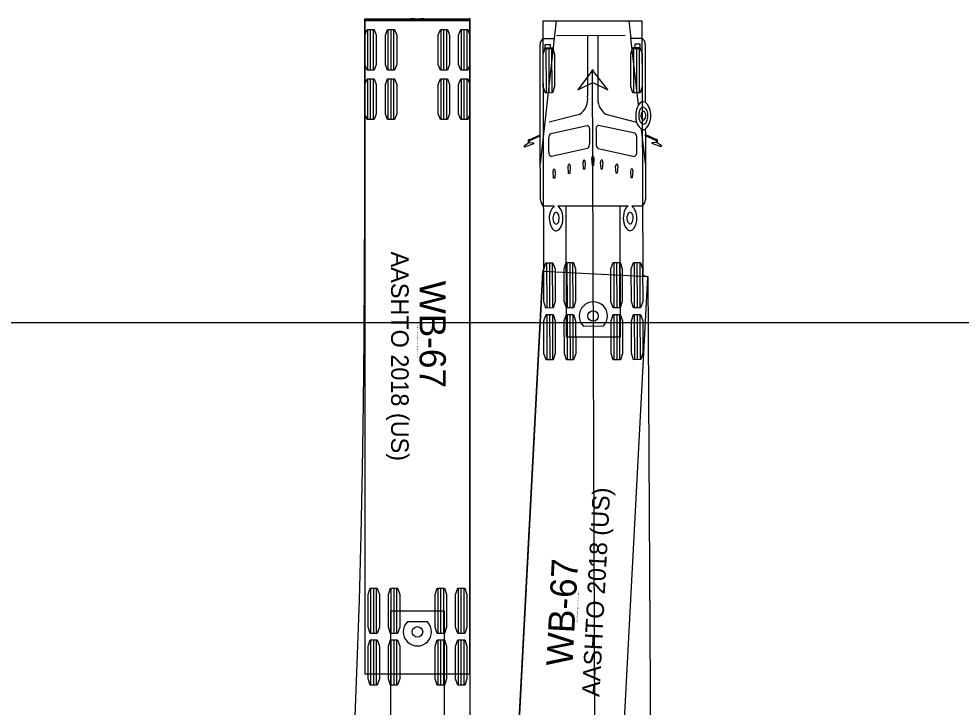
# Model space of a CAD drawing. Extents: x 973688 to 979179, y 703586 to 707602.
# Drawn here: x 976679.6 to 976755.9, y 705771.6 to 705827.3 of the extents above; entities that cross this region are included whole.
import ezdxf

# ---------------------------------------------------------------- set-up
doc = ezdxf.new("R2010")
doc.units = 0
for name, color, linetype in [('EB Left', 7, 'Continuous'), ('NO PLOT', 7, 'Continuous'), ('SB Right', 7, 'Continuous')]:
    doc.layers.add(name, color=color, linetype=linetype)

msp = doc.modelspace()

# ---------------------------------------------------------------- linework, layer by layer
at = {"layer": 'EB Left'}
for p, q in [((976721.836, 705815.557), (976722.969, 705825.695)), ((976728.694, 705825.935), (976723.131, 705825.92)), ((976725.641, 705825.927), (976725.654, 705821.035)), ((976726.475, 705825.929), (976726.488, 705821.038)), ((976729.78, 705820.321), (976729.148, 705825.711)), ((976722.219, 705825.213), (976722.631, 705825.214)), ((976722.22, 705824.857), (976722.219, 705825.213)), ((976722.632, 705824.858), (976722.22, 705824.857)), ((976722.288, 705824.952), (976722.301, 705821.285)), ((976722.518, 705824.953), (976722.53, 705821.286)), ((976722.631, 705825.214), (976722.632, 705824.858)), ((976722.747, 705824.954), (976722.759, 705821.287)), ((976729.372, 705824.972), (976729.384, 705821.305)), ((976729.9, 705825.234), (976729.488, 705825.232)), ((976729.488, 705825.232), (976729.489, 705824.876)), ((976729.489, 705824.876), (976729.901, 705824.878)), ((976729.601, 705824.973), (976729.613, 705821.306)), ((976729.83, 705824.973), (976729.842, 705821.307)), ((976729.901, 705824.878), (976729.9, 705825.234)), ((976726.438, 705710.847), (976726.065, 705823.129)), ((976725.005, 705819.554), (976722.54, 705818.915)), ((976727.144, 705819.56), (976729.626, 705818.931)), ((976722.686, 705818.011), (976725.62, 705818.664)), ((976729.472, 705818.03), (976726.534, 705818.666)), ((976721.83, 705817.807), (976721.829, 705817.907)), ((976725.819, 705818.294), (976725.822, 705817.164)), ((976726.337, 705818.296), (976726.34, 705817.165)), ((976730.336, 705815.58), (976730.009, 705818.367)), ((976730.33, 705817.829), (976730.329, 705817.93)), ((976720.894, 705817.281), (976720.872, 705817.265)), ((976720.922, 705817.28), (976720.894, 705817.281)), ((976722.525, 705816.51), (976722.522, 705817.641)), ((976729.641, 705816.529), (976729.638, 705817.66)), ((976731.24, 705817.308), (976731.268, 705817.309)), ((976731.268, 705817.309), (976731.29, 705817.293)), ((976725.658, 705816.793), (976722.724, 705816.14)), ((976726.507, 705816.795), (976729.445, 705816.158)), ((976725.335, 705815.121), (976725.295, 705815.67)), ((976725.463, 705815.671), (976725.425, 705815.121)), ((976726.041, 705815.431), (976726, 705815.981)), ((976726.169, 705815.981), (976726.131, 705815.431)), ((976726.748, 705815.124), (976726.708, 705815.674)), ((976726.876, 705815.674), (976726.838, 705815.125)), ((976722.902, 705814.394), (976722.862, 705814.944)), ((976723.03, 705814.944), (976722.992, 705814.394)), ((976724.119, 705814.783), (976724.077, 705815.358)), ((976724.209, 705814.783), (976724.119, 705814.783)), ((976724.246, 705815.358), (976724.209, 705814.783)), ((976725.425, 705815.121), (976725.335, 705815.121)), ((976726.131, 705815.431), (976726.041, 705815.431)), ((976726.838, 705815.125), (976726.748, 705815.124)), ((976727.967, 705814.793), (976727.926, 705815.343)), ((976728.057, 705814.794), (976727.967, 705814.793)), ((976728.094, 705815.343), (976728.057, 705814.794)), ((976729.185, 705814.411), (976729.144, 705814.961)), ((976729.313, 705814.961), (976729.275, 705814.411)), ((976722.992, 705814.394), (976722.902, 705814.394)), ((976729.275, 705814.411), (976729.185, 705814.411)), ((976728.26, 705812.135), (976723.93, 705812.124)), ((976722.336, 705807.553), (976722.346, 705803.886)), ((976722.566, 705807.553), (976722.575, 705803.887)), ((976722.795, 705807.554), (976722.805, 705803.887)), ((976723.986, 705807.557), (976723.996, 705803.89)), ((976724.216, 705807.558), (976724.225, 705803.891)), ((976724.445, 705807.558), (976724.455, 705803.892)), ((976727.77, 705807.567), (976727.78, 705803.901)), ((976727.999, 705807.568), (976728.009, 705803.901)), ((976728.228, 705807.568), (976728.238, 705803.902)), ((976729.42, 705807.572), (976729.43, 705803.905)), ((976729.649, 705807.572), (976729.659, 705803.906)), ((976729.878, 705807.573), (976729.888, 705803.906)), ((976722.348, 705803.353), (976722.358, 705799.686)), ((976722.577, 705803.353), (976722.587, 705799.687)), ((976722.806, 705803.354), (976722.816, 705799.687)), ((976723.998, 705803.357), (976724.008, 705799.69)), ((976724.227, 705803.358), (976724.237, 705799.691)), ((976724.456, 705803.358), (976724.466, 705799.692)), ((976727.781, 705803.367), (976727.791, 705799.701)), ((976728.01, 705803.368), (976728.02, 705799.701)), ((976728.239, 705803.369), (976728.249, 705799.702)), ((976729.431, 705803.372), (976729.441, 705799.705)), ((976729.66, 705803.372), (976729.67, 705799.706)), ((976729.889, 705803.373), (976729.899, 705799.706)), ((976725.318, 705802.429), (976726.934, 705802.433))]:
    msp.add_line(p, q, dxfattribs=at)
for points in [[(976716.95, 705725.889), (976717.493, 705731.11), (976717.977, 705736.349), (976718.407, 705741.602), (976718.79, 705746.867), (976719.129, 705752.126), (976719.424, 705757.292), (976722.031, 705806.849), (976722.11, 705806.976), (976722.055, 705827.119), (976730.055, 705827.132), (976730.128, 705806.546), (976730.519, 705806.402), (976730.78, 705763.535), (976730.818, 705753.054), (976730.814, 705742.33), (976730.784, 705736.924), (976730.706, 705730.152), (976730.816, 705724.697)], [(976722.103, 705825.692), (976722.96, 705825.694), (976722.969, 705825.696), (976723.128, 705827.121), (976723.191, 705827.122), (976726.054, 705827.129), (976728.918, 705827.137), (976728.981, 705827.137), (976729.148, 705825.713), (976729.157, 705825.711), (976730.014, 705825.713)], [(976720.916, 705817.486), (976721.82, 705817.903), (976721.829, 705817.915), (976721.809, 705825.171)], [(976730.31, 705825.194), (976730.322, 705820.55)], [(976726.065, 705823.129), (976724.853, 705821.539), (976726.069, 705822.129), (976727.288, 705821.547), (976726.065, 705823.129)], [(976730.328, 705818.364), (976730.329, 705817.938), (976730.338, 705817.926), (976731.245, 705817.514)], [(976731.289, 705817.38), (976731.29, 705817.294), (976731.292, 705817.291), (976731.61, 705817.054), (976731.613, 705817.052), (976731.613, 705816.933), (976731.611, 705816.933), (976730.891, 705817.188), (976730.891, 705817.291), (976731.239, 705817.308), (976731.24, 705817.309), (976731.239, 705817.389), (976731.239, 705817.39), (976731.239, 705817.39), (976731.227, 705817.427), (976731.226, 705817.427), (976730.33, 705817.829), (976730.344, 705812.653)], [(976721.843, 705812.631), (976721.83, 705817.807), (976720.935, 705817.399), (976720.935, 705817.399), (976720.923, 705817.362), (976720.922, 705817.362), (976720.922, 705817.361), (976720.922, 705817.281), (976720.923, 705817.28), (976721.271, 705817.265), (976721.271, 705817.162), (976720.553, 705816.903), (976720.551, 705816.904), (976720.551, 705817.022), (976720.553, 705817.025), (976720.87, 705817.263), (976720.872, 705817.266), (976720.872, 705817.352)], [(976722.961, 705812.121), (976722.116, 705812.119)], [(976728.947, 705812.137), (976728.261, 705812.135), (976728.261, 705811.897), (976728.289, 705801.535), (976726.123, 705801.529), (976723.958, 705801.524), (976723.93, 705811.885), (976723.929, 705812.124), (976723.243, 705812.122)], [(976730.074, 705812.14), (976729.228, 705812.138)], [(976727.717, 705753.547), (976727.738, 705753.546), (976727.742, 705753.616), (976728.04, 705759.276), (976730.519, 705806.402), (976726.275, 705806.625), (976722.031, 705806.849), (976719.552, 705759.722), (976719.255, 705754.063), (976719.252, 705753.992), (976719.273, 705753.991)]]:
    msp.add_lwpolyline(points, dxfattribs=at)
for points in [[(976722.232, 705824.952), (976722.804, 705824.954), (976722.978, 705824.441), (976722.986, 705821.801), (976722.816, 705821.287), (976722.244, 705821.285), (976722.07, 705821.798), (976722.061, 705824.438)], [(976729.315, 705824.972), (976729.887, 705824.973), (976730.061, 705824.461), (976730.07, 705821.821), (976729.899, 705821.307), (976729.327, 705821.305), (976729.153, 705821.818), (976729.144, 705824.458)], [(976726.065, 705823.129), (976724.853, 705821.539), (976726.069, 705822.129), (976727.288, 705821.547)], [(976722.28, 705807.552), (976722.852, 705807.554), (976723.025, 705807.041), (976723.032, 705804.401), (976722.861, 705803.887), (976722.289, 705803.886), (976722.116, 705804.399), (976722.109, 705807.039)], [(976723.93, 705807.557), (976724.502, 705807.558), (976724.675, 705807.046), (976724.682, 705804.406), (976724.511, 705803.892), (976723.939, 705803.89), (976723.766, 705804.403), (976723.759, 705807.043)], [(976727.713, 705807.567), (976728.285, 705807.569), (976728.459, 705807.056), (976728.466, 705804.416), (976728.295, 705803.902), (976727.723, 705803.9), (976727.549, 705804.413), (976727.542, 705807.053)], [(976729.363, 705807.572), (976729.935, 705807.573), (976730.109, 705807.06), (976730.116, 705804.42), (976729.945, 705803.906), (976729.373, 705803.905), (976729.199, 705804.418), (976729.192, 705807.058)], [(976722.291, 705803.352), (976722.863, 705803.354), (976723.037, 705802.841), (976723.044, 705800.201), (976722.873, 705799.687), (976722.301, 705799.686), (976722.127, 705800.199), (976722.12, 705802.839)], [(976723.941, 705803.357), (976724.513, 705803.358), (976724.687, 705802.846), (976724.694, 705800.206), (976724.523, 705799.692), (976723.951, 705799.69), (976723.777, 705800.203), (976723.77, 705802.843)], [(976727.724, 705803.367), (976728.296, 705803.369), (976728.47, 705802.856), (976728.477, 705800.216), (976728.306, 705799.702), (976727.734, 705799.7), (976727.56, 705800.213), (976727.553, 705802.853)], [(976729.374, 705803.372), (976729.946, 705803.373), (976730.12, 705802.86), (976730.127, 705800.22), (976729.956, 705799.706), (976729.384, 705799.705), (976729.21, 705800.218), (976729.203, 705802.858)]]:
    msp.add_lwpolyline(points, close=True, dxfattribs=at)
for centre, radius in [((976726.065, 705823.129), 0.0417), ((976726.097, 705803.242), 0.424)]:
    msp.add_circle(centre, radius, dxfattribs=at)
for centre, radius, start, end in [((976722.29, 705825.244), 0.486, 112.61722, 188.56833), ((976729.829, 705825.264), 0.486, 351.74019, 67.69129), ((976724.154, 705820.809), 1.517, 304.1468, 8.57421), ((976727.989, 705820.82), 1.517, 171.7343, 236.16172), ((976731.256, 705819.471), 1.704, 150.07494, 185.98301), ((976730.164, 705820.14), 0.425, 68.21719, 154.75355), ((976730.217, 705819.774), 0.366, 98.2066, 170.68758), ((976729.915, 705819.553), 0.634, 350.73812, 66.73984), ((976729.253, 705819.455), 1.53, 314.647, 45.65604), ((976730.983, 705819.451), 1.189, 161.28546, 197.17478), ((976730.549, 705819.45), 0.575, 153.22937, 189.79971), ((976730.18, 705819.647), 0.158, 95.12548, 156.63823), ((976730.116, 705819.586), 0.223, 7.38916, 76.99165), ((976729.77, 705819.454), 0.589, 332.90979, 15.8925), ((976729.511, 705819.427), 1.03, 332.97791, 1.36442), ((976725.536, 705818.38), 0.296, 343.13782, 73.4355), ((976726.62, 705818.383), 0.296, 106.87302, 197.17069), ((976730.698, 705819.271), 1.136, 178.8588, 232.66137), ((976730.277, 705819.191), 0.44, 191.9485, 255.76135), ((976730.245, 705819.348), 0.263, 179.08917, 252.99109), ((976730.145, 705819.265), 0.17, 277.82332, 331.88766), ((976730.136, 705819.079), 0.317, 276.00445, 337.59685), ((976722.905, 705817.693), 0.387, 124.48711, 187.71907), ((976729.255, 705817.71), 0.387, 352.58944, 55.82141), ((976730.169, 705818.675), 0.347, 242.48147, 297.29205), ((976720.958, 705817.417), 0.108, 170.99543, 217.17793), ((976720.904, 705817.435), 0.0522, 76.41704, 181.27166), ((976725.439, 705817.112), 0.387, 304.48956, 7.71662), ((976726.724, 705817.115), 0.387, 172.59189, 235.81896), ((976731.257, 705817.463), 0.0522, 359.03686, 103.89147), ((976731.203, 705817.445), 0.108, 323.13059, 9.31309), ((976722.851, 705816.447), 0.332, 169.07566, 247.49766), ((976729.316, 705816.464), 0.332, 292.81085, 11.23285), ((976725.441, 705815.726), 0.157, 113.70024, 200.8099), ((976725.284, 705815.712), 0.184, 347.10744, 58.99945), ((976726.147, 705816.036), 0.157, 113.70024, 200.8099), ((976726.022, 705816.036), 0.157, 339.49862, 66.60828), ((976726.887, 705815.716), 0.184, 121.30906, 193.20108), ((976726.729, 705815.729), 0.157, 339.49862, 66.60828), ((976728.105, 705815.385), 0.184, 121.30906, 193.20108), ((976727.947, 705815.398), 0.157, 339.49862, 66.60828), ((976723.008, 705814.999), 0.157, 113.70024, 200.8099), ((976722.851, 705814.985), 0.184, 347.10744, 58.99945), ((976724.225, 705815.388), 0.157, 113.70024, 200.8099), ((976724.067, 705815.374), 0.184, 347.10744, 58.99945), ((976729.324, 705815.003), 0.184, 121.30906, 193.20108), ((976729.166, 705815.016), 0.157, 339.49862, 66.60828), ((976722.462, 705812.632), 0.619, 180.15224, 235.99395), ((976729.724, 705812.652), 0.619, 304.31457, 0.15628), ((976723.688, 705811.248), 1.136, 129.78419, 184.57549), ((976722.862, 705811.501), 0.729, 15.96274, 58.47674), ((976729.331, 705811.518), 0.729, 121.83178, 164.34577), ((976728.506, 705811.261), 1.136, 355.73303, 50.52432), ((976723.971, 705811.11), 1.416, 178.08241, 215.15026), ((976723.512, 705811.13), 0.664, 175.05809, 213.2798), ((976723.372, 705811.208), 0.522, 135.15962, 182.32375), ((976723.107, 705811.445), 0.169, 28.58858, 128.7073), ((976722.632, 705811.143), 0.732, 345.32808, 31.56252), ((976721.925, 705811.144), 1.73, 353.9809, 18.7794), ((976730.27, 705811.166), 1.73, 161.52911, 186.32762), ((976729.685, 705811.033), 1.136, 182.86955, 224.39029), ((976729.563, 705811.162), 0.732, 148.746, 194.98044), ((976729.216, 705811.015), 0.362, 186.81672, 235.8577), ((976729.086, 705811.461), 0.169, 51.60121, 151.71993), ((976728.823, 705811.223), 0.522, 357.98477, 45.14889), ((976728.683, 705811.144), 0.664, 327.02871, 5.25043), ((976728.224, 705811.121), 1.416, 325.15825, 2.22611), ((976723.102, 705810.486), 0.346, 213.54696, 310.56001), ((976723.105, 705810.853), 0.172, 210.45586, 297.60645), ((976722.98, 705810.999), 0.362, 304.45082, 353.4918), ((976722.511, 705811.013), 1.136, 315.91822, 357.43897), ((976729.097, 705810.502), 0.346, 229.74851, 326.76156), ((976729.092, 705810.869), 0.172, 242.70206, 329.85266), ((976726.124, 705803.239), 1.143, 315.15426, 225.15426)]:
    msp.add_arc(centre, radius, start, end, dxfattribs=at)
for centre, major_axis, start_param, end_param in [((976720.893, 705817.42), (-0.0002, 0.0782), 2.615166, 3.884468), ((976720.893, 705817.42), (0.0002, -0.0782), 1.301202, 2.571945), ((976731.268, 705817.448), (-0.0002, 0.0782), 0.569648, 1.840391), ((976731.268, 705817.448), (-0.0002, 0.0782), 2.398717, 3.668019)]:
    msp.add_ellipse(centre, major_axis=major_axis, ratio=0.544872, start_param=start_param, end_param=end_param, dxfattribs=at)
at = {"layer": 'NO PLOT'}
msp.add_lwpolyline([(976318.336, 705802.708), (976998.336, 705802.708), (976998.336, 705362.708), (976318.336, 705362.708)], close=True, dxfattribs=at)
at = {"layer": 'SB Right'}
for p, q in [((976707.637, 705827.146), (976716.137, 705827.146)), ((976711.356, 705827.216), (976711.621, 705827.216)), ((976711.887, 705827.216), (976711.887, 705827.146)), ((976712.153, 705827.216), (976712.418, 705827.216)), ((976707.866, 705823.137), (976707.866, 705826.437)), ((976708.095, 705823.137), (976708.095, 705826.437)), ((976708.324, 705823.137), (976708.324, 705826.437)), ((976709.516, 705823.137), (976709.516, 705826.437)), ((976709.745, 705823.137), (976709.745, 705826.437)), ((976709.974, 705823.137), (976709.974, 705826.437)), ((976713.799, 705823.137), (976713.799, 705826.437)), ((976714.029, 705823.137), (976714.029, 705826.437)), ((976714.258, 705823.137), (976714.258, 705826.437)), ((976715.449, 705823.137), (976715.449, 705826.437)), ((976715.679, 705823.137), (976715.679, 705826.437)), ((976715.908, 705823.137), (976715.908, 705826.437)), ((976707.866, 705819.137), (976707.866, 705822.437)), ((976708.095, 705819.137), (976708.095, 705822.437)), ((976708.324, 705819.137), (976708.324, 705822.437)), ((976709.516, 705819.137), (976709.516, 705822.437)), ((976709.745, 705819.137), (976709.745, 705822.437)), ((976709.974, 705819.137), (976709.974, 705822.437)), ((976713.799, 705819.137), (976713.799, 705822.437)), ((976714.029, 705819.137), (976714.029, 705822.437)), ((976714.258, 705819.137), (976714.258, 705822.437)), ((976715.449, 705819.137), (976715.449, 705822.437)), ((976715.679, 705819.137), (976715.679, 705822.437)), ((976715.908, 705819.137), (976715.908, 705822.437)), ((976708.116, 705777.554), (976708.116, 705781.22)), ((976708.345, 705777.554), (976708.345, 705781.22)), ((976708.574, 705777.554), (976708.574, 705781.22)), ((976709.766, 705777.554), (976709.766, 705781.22)), ((976709.995, 705777.554), (976709.995, 705781.22)), ((976710.224, 705777.554), (976710.224, 705781.22)), ((976713.549, 705777.554), (976713.549, 705781.22)), ((976713.779, 705777.554), (976713.779, 705781.22)), ((976714.008, 705777.554), (976714.008, 705781.22)), ((976715.199, 705777.554), (976715.199, 705781.22)), ((976715.429, 705777.554), (976715.429, 705781.22)), ((976715.658, 705777.554), (976715.658, 705781.22)), ((976712.69, 705778.485), (976711.074, 705778.485)), ((976708.116, 705773.354), (976708.116, 705777.02)), ((976708.345, 705773.354), (976708.345, 705777.02)), ((976708.574, 705773.354), (976708.574, 705777.02)), ((976709.766, 705773.354), (976709.766, 705777.02)), ((976709.995, 705773.354), (976709.995, 705777.02)), ((976710.224, 705773.354), (976710.224, 705777.02)), ((976713.549, 705773.354), (976713.549, 705777.02)), ((976713.779, 705773.354), (976713.779, 705777.02)), ((976714.008, 705773.354), (976714.008, 705777.02)), ((976715.199, 705773.354), (976715.199, 705777.02)), ((976715.429, 705773.354), (976715.429, 705777.02)), ((976715.658, 705773.354), (976715.658, 705777.02))]:
    msp.add_line(p, q, dxfattribs=at)
for points in [[(976706.815, 705770.088), (976707.018, 705775.124), (976707.185, 705780.248), (976707.325, 705785.521), (976707.434, 705790.832), (976707.516, 705796.146), (976707.572, 705801.465), (976707.628, 705812.117), (976707.637, 705827.287), (976716.137, 705827.287), (976716.137, 705827.13), (976716.137, 705827.13)], [(976707.659, 705827.216), (976707.638, 705827.216), (976707.638, 705827.146), (976707.637, 705821.479), (976707.637, 705774.287), (976711.887, 705774.287), (976716.137, 705774.287), (976716.137, 705821.479), (976716.136, 705827.146), (976716.136, 705827.216), (976716.114, 705827.216)], [(976711.624, 705827.287), (976711.357, 705827.287), (976711.356, 705827.286), (976711.356, 705827.217), (976711.32, 705827.216), (976707.684, 705827.216), (976707.683, 705827.217)], [(976712.146, 705827.216), (976711.625, 705827.217)], [(976716.09, 705827.217), (976716.089, 705827.216), (976712.454, 705827.216), (976712.418, 705827.217), (976712.418, 705827.286), (976712.417, 705827.287), (976712.15, 705827.287)], [(976716.137, 705827.13), (976716.137, 705775.112), (976716.119, 705770.286), (976716.047, 705765.115), (976715.887, 705758.595), (976715.883, 705753.697), (976715.619, 705748.5), (976715.302, 705743.308), (976714.94, 705738.196), (976714.521, 705733.032), (976714.039, 705727.751)], [(976709.035, 705768.787), (976709.721, 705768.787), (976709.722, 705769.025), (976709.722, 705779.387), (976711.887, 705779.387), (976714.052, 705779.387), (976714.052, 705769.025), (976714.053, 705768.787), (976714.739, 705768.787)]]:
    msp.add_lwpolyline(points, dxfattribs=at)
for points in [[(976708.381, 705823.137), (976707.809, 705823.137), (976707.637, 705823.599), (976707.637, 705825.975), (976707.809, 705826.437), (976708.381, 705826.437), (976708.554, 705825.975), (976708.554, 705823.599)], [(976710.031, 705823.137), (976709.459, 705823.137), (976709.287, 705823.599), (976709.287, 705825.975), (976709.459, 705826.437), (976710.031, 705826.437), (976710.204, 705825.975), (976710.204, 705823.599)], [(976714.315, 705823.137), (976713.743, 705823.137), (976713.57, 705823.599), (976713.57, 705825.975), (976713.743, 705826.437), (976714.315, 705826.437), (976714.487, 705825.975), (976714.487, 705823.599)], [(976715.965, 705823.137), (976715.393, 705823.137), (976715.22, 705823.599), (976715.22, 705825.975), (976715.393, 705826.437), (976715.965, 705826.437), (976716.137, 705825.975), (976716.137, 705823.599)], [(976708.381, 705819.137), (976707.809, 705819.137), (976707.637, 705819.599), (976707.637, 705821.975), (976707.809, 705822.437), (976708.381, 705822.437), (976708.554, 705821.975), (976708.554, 705819.599)], [(976710.031, 705819.137), (976709.459, 705819.137), (976709.287, 705819.599), (976709.287, 705821.975), (976709.459, 705822.437), (976710.031, 705822.437), (976710.204, 705821.975), (976710.204, 705819.599)], [(976714.315, 705819.137), (976713.743, 705819.137), (976713.57, 705819.599), (976713.57, 705821.975), (976713.743, 705822.437), (976714.315, 705822.437), (976714.487, 705821.975), (976714.487, 705819.599)], [(976715.965, 705819.137), (976715.393, 705819.137), (976715.22, 705819.599), (976715.22, 705821.975), (976715.393, 705822.437), (976715.965, 705822.437), (976716.137, 705821.975), (976716.137, 705819.599)], [(976708.631, 705777.554), (976708.059, 705777.554), (976707.887, 705778.067), (976707.887, 705780.707), (976708.059, 705781.22), (976708.631, 705781.22), (976708.804, 705780.707), (976708.804, 705778.067)], [(976710.281, 705777.554), (976709.709, 705777.554), (976709.537, 705778.067), (976709.537, 705780.707), (976709.709, 705781.22), (976710.281, 705781.22), (976710.454, 705780.707), (976710.454, 705778.067)], [(976714.065, 705777.554), (976713.493, 705777.554), (976713.32, 705778.067), (976713.32, 705780.707), (976713.493, 705781.22), (976714.065, 705781.22), (976714.237, 705780.707), (976714.237, 705778.067)], [(976715.715, 705777.554), (976715.143, 705777.554), (976714.97, 705778.067), (976714.97, 705780.707), (976715.143, 705781.22), (976715.715, 705781.22), (976715.887, 705780.707), (976715.887, 705778.067)], [(976708.631, 705773.354), (976708.059, 705773.354), (976707.887, 705773.867), (976707.887, 705776.507), (976708.059, 705777.02), (976708.631, 705777.02), (976708.804, 705776.507), (976708.804, 705773.867)], [(976710.281, 705773.354), (976709.709, 705773.354), (976709.537, 705773.867), (976709.537, 705776.507), (976709.709, 705777.02), (976710.281, 705777.02), (976710.454, 705776.507), (976710.454, 705773.867)], [(976714.065, 705773.354), (976713.493, 705773.354), (976713.32, 705773.867), (976713.32, 705776.507), (976713.493, 705777.02), (976714.065, 705777.02), (976714.237, 705776.507), (976714.237, 705773.867)], [(976715.715, 705773.354), (976715.143, 705773.354), (976714.97, 705773.867), (976714.97, 705776.507), (976715.143, 705777.02), (976715.715, 705777.02), (976715.887, 705776.507), (976715.887, 705773.867)]]:
    msp.add_lwpolyline(points, close=True, dxfattribs=at)
for centre, radius in [((976707.671, 705827.251), 0.0266), ((976716.103, 705827.251), 0.0266), ((976711.887, 705777.675), 0.424)]:
    msp.add_circle(centre, radius, dxfattribs=at)
for centre, radius, start, end in [((976707.659, 705829.238), 2.022, 270, 270.68376), ((976711.623, 705827.252), 0.0354, 94.29154, 266.477), ((976711.624, 705827.252), 0.0352, 270.97432, 89.97473), ((976712.15, 705827.252), 0.0352, 90.02527, 269.02568), ((976712.15, 705827.252), 0.0353, 273.33618, 91.68583), ((976716.103, 705827.251), 0.0363, 289.07745, 250.23879), ((976711.882, 705777.677), 1.143, 135, 45)]:
    msp.add_arc(centre, radius, start, end, dxfattribs=at)

# ---------------------------------------------------------------- texts
at = {"layer": 'EB Left'}
for s, height, p in [('AASHTO 2018 (US)', 1.41667, (976726.61, 705772.395)), ('WB-67', 2.125, (976724.434, 705774.866)), ('(c) 2020 Transoft Solutions, Inc. All rights reserved.', 0.085, (976724.834, 705778.422))]:
    msp.add_text(s, height=height, rotation=86.98876, dxfattribs=at).set_placement(p)
at = {"layer": 'SB Right'}
for s, height, p in [('AASHTO 2018 (US)', 1.41667, (976709.755, 705808.452)), ('WB-67', 2.125, (976712.057, 705806.1)), ('(c) 2020 Transoft Solutions, Inc. All rights reserved.', 0.085, (976711.844, 705802.527))]:
    msp.add_text(s, height=height, rotation=270, dxfattribs=at).set_placement(p)

doc.saveas('drawing.dxf')
